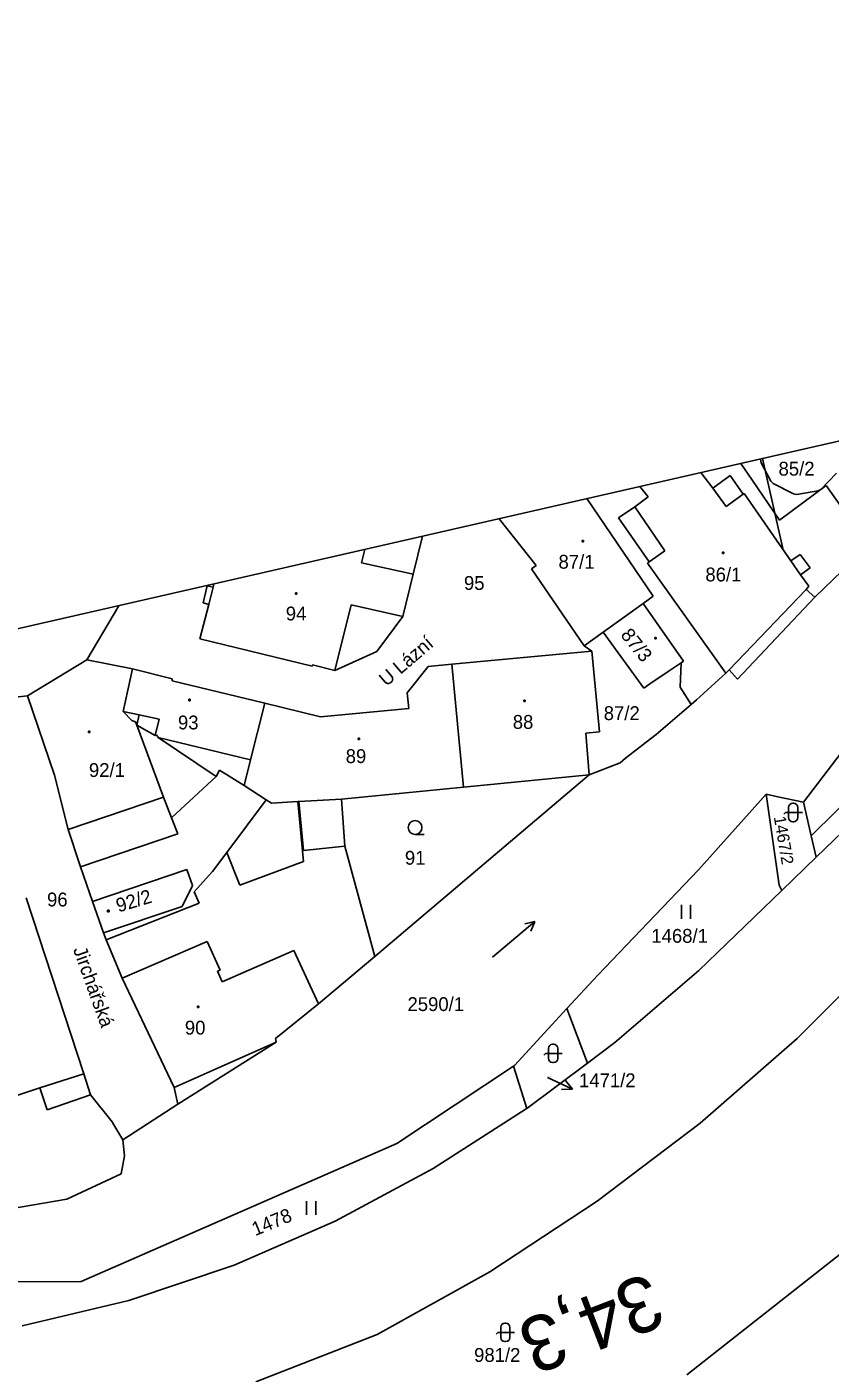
# Model space of a CAD drawing. Extents: x -805730 to -804640, y -1150889 to -1150366.
# Drawn here: x -805195.8 to -805108.7, y -1150558.7 to -1150412.8 of the extents above; entities that cross this region are included whole.
import ezdxf

# ---------------------------------------------------------------- set-up
doc = ezdxf.new("R2010")
doc.units = 0
for name, color, linetype in [('Default', 7, 'Continuous'), ('formát', 7, 'Continuous'), ('kilometráž - vrstava 7', 7, 'Continuous'), ('kn_celek - Cisla parcel pomocna', 7, 'Continuous'), ('kn_celek - Cisla pozemkovych parcel', 7, 'Continuous'), ('kn_celek - Cisla stavebnich parcel', 7, 'Continuous'), ('kn_celek - Dalsi prvky mapy popis', 7, 'Continuous'), ('kn_celek - Hranice parcel', 7, 'Continuous'), ('kn_celek - Vnitrni kresby', 7, 'Continuous'), ('kn_celek - Znacky budov', 7, 'Continuous'), ('kn_celek - Znacky kultur', 7, 'Continuous')]:
    doc.layers.add(name, color=color, linetype=linetype)

# ---------------------------------------------------------------- blocks, each defined once
blk = doc.blocks.new('304')
at = {"layer": 'Default'}
blk.add_line((-0.1, 0), (9.9, 0), dxfattribs=at)
blk.add_circle((-0.1, 7.5), 7.5, dxfattribs=at)
blk = doc.blocks.new('316')
at = {"layer": 'Default'}
for p, q in [((-5, 15.5), (-5, 4.5)), ((0.5, 20), (-0.5, 20)), ((5, 4.5), (5, 15.5)), ((-8.3, 10), (-10, 8.1)), ((-5, 10), (-8.3, 10)), ((-5, 10), (5, 10)), ((-0.5, 0), (0.5, 0)), ((10, 10), (5, 10))]:
    blk.add_line(p, q, dxfattribs=at)
for centre, start, end in [((-0.5, 15.5), 90, 180), ((0.5, 15.5), 0, 90), ((-0.5, 4.5), 180, 270), ((0.5, 4.5), 270, 0)]:
    blk.add_arc(centre, 4.5, start, end, dxfattribs=at)
blk = doc.blocks.new('306')
at = {"layer": 'Default'}
for p, q in [((-5.2, 0), (-5.2, 15)), ((4.8, 0), (4.8, 15))]:
    blk.add_line(p, q, dxfattribs=at)
blk = doc.blocks.new('802')
at = {"layer": 'Default'}
for p, q in [((-30, 0), (30, 0)), ((20, 5), (30, 0)), ((30, 0), (20, -5))]:
    blk.add_line(p, q, dxfattribs=at)
blk = doc.blocks.new('402')
at = {"layer": 'Default'}
for p, q in [((-0.8, 0.8), (0.7, 0.8)), ((-0.8, 0.8), (-0.8, -0.7)), ((0.7, 0.8), (0.7, -0.7)), ((0.7, -0.7), (-0.8, -0.7))]:
    blk.add_line(p, q, dxfattribs=at)
blk = doc.blocks.new('Z61')
at = {"layer": 'Default'}
for p, q in [((0, 0), (30, 0)), ((30, 0), (19.2, 5.3)), ((30, 0), (19.2, -5.3))]:
    blk.add_line(p, q, dxfattribs=at)

msp = doc.modelspace()

# ---------------------------------------------------------------- linework, layer by layer
at = {"layer": 'formát'}
for p, q in [((-804911.33, -1150412.76), (-805116.05, -1150459.54)), ((-805116.05, -1150459.54), (-805730.21, -1150599.91)), ((-805116.05, -1150459.54), (-805113.82, -1150469.29))]:
    msp.add_line(p, q, dxfattribs=at)
at = {"layer": 'kn_celek - Hranice parcel'}
for p, q in [((-805117.2, -1150461.8), (-805118.38, -1150460.08)), ((-805116.25, -1150459.59), (-805116.25, -1150459.6)), ((-805116.25, -1150459.6), (-805116.18, -1150459.99)), ((-805116.18, -1150459.99), (-805115.13, -1150462.01)), ((-805122.71, -1150461.07), (-805121.43, -1150462.77)), ((-805121.43, -1150462.77), (-805119.54, -1150461.39)), ((-805119.54, -1150461.39), (-805118.15, -1150463.41)), ((-805114.18, -1150466.22), (-805117.2, -1150461.8)), ((-805115.13, -1150462.01), (-805114.9, -1150462.24)), ((-805114.9, -1150462.24), (-805112.68, -1150463.36)), ((-805109.72, -1150462.89), (-805108.02, -1150461.11)), ((-805129.88, -1150464.79), (-805128.44, -1150463.7)), ((-805128.44, -1150463.7), (-805129.33, -1150462.58)), ((-805118.15, -1150463.41), (-805118.02, -1150463.32)), ((-805112.97, -1150470.62), (-805118.02, -1150463.32)), ((-805109.13, -1150462.48), (-805114.18, -1150466.22)), ((-805112.68, -1150463.36), (-805112.35, -1150463.44)), ((-805112.35, -1150463.44), (-805109.99, -1150463.04)), ((-805109.99, -1150463.04), (-805109.72, -1150462.89)), ((-805109.13, -1150462.48), (-805105.81, -1150467.16)), ((-805135.07, -1150463.89), (-805127.89, -1150474.45)), ((-805131.65, -1150465.97), (-805129.88, -1150464.79)), ((-805140.59, -1150471.14), (-805144.58, -1150466.07)), ((-805128.33, -1150470.75), (-805131.65, -1150465.97)), ((-805153.92, -1150472.09), (-805152.91, -1150467.97)), ((-805104.72, -1150469.11), (-805110.36, -1150474.57)), ((-805141.07, -1150471.5), (-805140.59, -1150471.14)), ((-805128.5, -1150470.88), (-805128.33, -1150470.75)), ((-805120.01, -1150482.82), (-805128.5, -1150470.88)), ((-805112.97, -1150470.62), (-805111.96, -1150469.93)), ((-805111.96, -1150469.93), (-805110.87, -1150471.39)), ((-805153.92, -1150472.09), (-805155.04, -1150476.68)), ((-805135.36, -1150479.83), (-805141.07, -1150471.5)), ((-805110.87, -1150471.39), (-805111.93, -1150472.13)), ((-805111.93, -1150472.13), (-805111.01, -1150473.36)), ((-805176.25, -1150473.34), (-805176.67, -1150475.17)), ((-805175.59, -1150473.5), (-805176.25, -1150473.34)), ((-805175.59, -1150473.5), (-805175.5, -1150473.13)), ((-805111.01, -1150473.36), (-805111.3, -1150473.72)), ((-805111.3, -1150473.72), (-805110.36, -1150474.57)), ((-805185.81, -1150475.49), (-805189.27, -1150481.37)), ((-805176.05, -1150475.37), (-805177.02, -1150479.09)), ((-805176.67, -1150475.17), (-805176.05, -1150475.37)), ((-805133.32, -1150478.36), (-805128.99, -1150475.24)), ((-805127.89, -1150474.45), (-805128.99, -1150475.24)), ((-805124.61, -1150481.5), (-805128.99, -1150475.24)), ((-805110.36, -1150474.57), (-805118.75, -1150483.44)), ((-805155.04, -1150476.68), (-805157.86, -1150480.45)), ((-805111.59, -1150496.78), (-805095.74, -1150475.92)), ((-805133.32, -1150478.36), (-805135.36, -1150479.83)), ((-805128.9, -1150484.42), (-805133.32, -1150478.36)), ((-805164.86, -1150482.06), (-805177.02, -1150479.09)), ((-805134.54, -1150480.41), (-805135.36, -1150479.83)), ((-805189.27, -1150481.37), (-805195.7, -1150485.27)), ((-805189.27, -1150481.37), (-805184.34, -1150482.34)), ((-805157.86, -1150480.45), (-805162.4, -1150482.51)), ((-805149.71, -1150481.83), (-805134.54, -1150480.41)), ((-805134.54, -1150480.41), (-805133.7, -1150489.18)), ((-805184.34, -1150482.34), (-805185.33, -1150486.97)), ((-805184.34, -1150482.34), (-805180.02, -1150483.43)), ((-805164.82, -1150481.92), (-805164.86, -1150482.06)), ((-805164.82, -1150481.92), (-805162.4, -1150482.51)), ((-805154.57, -1150484.94), (-805152.28, -1150482.08)), ((-805152.28, -1150482.08), (-805149.71, -1150481.83)), ((-805149.71, -1150481.83), (-805148.44, -1150495.16)), ((-805128.24, -1150483.97), (-805126.26, -1150482.62)), ((-805126.26, -1150482.62), (-805124.86, -1150481.67)), ((-805124.86, -1150481.67), (-805124.96, -1150484.31)), ((-805124.86, -1150481.67), (-805124.61, -1150481.5)), ((-805123.19, -1150485.7), (-805120.01, -1150482.82)), ((-805119.67, -1150482.46), (-805120.01, -1150482.82)), ((-805118.75, -1150483.44), (-805119.67, -1150482.46)), ((-805180.02, -1150483.43), (-805180.03, -1150483.62)), ((-805180.03, -1150483.62), (-805169.99, -1150486.07)), ((-805128.9, -1150484.42), (-805128.24, -1150483.97)), ((-805201.85, -1150485.93), (-805195.7, -1150485.27)), ((-805195.7, -1150485.27), (-805192.79, -1150493.88)), ((-805154.39, -1150486.64), (-805154.57, -1150484.94)), ((-805123.78, -1150486.2), (-805124.96, -1150484.31)), ((-805123.78, -1150486.2), (-805123.19, -1150485.7)), ((-805185.33, -1150486.97), (-805184.39, -1150487.94)), ((-805171.54, -1150492.19), (-805169.99, -1150486.07)), ((-805169.99, -1150486.07), (-805163.96, -1150487.55)), ((-805163.96, -1150487.55), (-805154.39, -1150486.64)), ((-805123.78, -1150486.2), (-805127.57, -1150489.47)), ((-805184.39, -1150487.94), (-805184, -1150488.09)), ((-805184, -1150488.09), (-805183.86, -1150488.46)), ((-805181.86, -1150489.58), (-805183.86, -1150488.46)), ((-805181.74, -1150489.49), (-805181.86, -1150489.58)), ((-805181.54, -1150489.78), (-805181.74, -1150489.49)), ((-805175.27, -1150494.02), (-805181.54, -1150489.78)), ((-805133.7, -1150489.18), (-805135.19, -1150489.32)), ((-805135.19, -1150489.32), (-805134.82, -1150493.83)), ((-805128.19, -1150489.93), (-805130.9, -1150492.03)), ((-805127.57, -1150489.47), (-805128.19, -1150489.93)), ((-805079.5, -1150489.41), (-805112.27, -1150522.42)), ((-805172.24, -1150494.99), (-805171.54, -1150492.19)), ((-805131.48, -1150492.51), (-805134.82, -1150493.83)), ((-805130.9, -1150492.03), (-805131.48, -1150492.51)), ((-805192.79, -1150493.88), (-805191.31, -1150499.74)), ((-805174.88, -1150493.33), (-805175.27, -1150494.02)), ((-805172.24, -1150494.99), (-805174.88, -1150493.33)), ((-805134.82, -1150493.83), (-805158.07, -1150513.5)), ((-805148.44, -1150495.16), (-805134.82, -1150493.83)), ((-805110.75, -1150500.43), (-805104.33, -1150494.08)), ((-805169.85, -1150496.54), (-805172.24, -1150494.99)), ((-805161.69, -1150496.45), (-805148.44, -1150495.16)), ((-805122.96, -1150504.14), (-805115.65, -1150495.91)), ((-805115.65, -1150495.91), (-805114.37, -1150496.22)), ((-805115.65, -1150495.91), (-805114.23, -1150505.8)), ((-805110.22, -1150502.75), (-805102.8, -1150495.57)), ((-805169.85, -1150496.54), (-805174.1, -1150502.23)), ((-805169.26, -1150496.89), (-805169.85, -1150496.54)), ((-805166.42, -1150496.73), (-805169.26, -1150496.89)), ((-805166.28, -1150496.72), (-805166.42, -1150496.73)), ((-805161.69, -1150496.45), (-805166.28, -1150496.72)), ((-805161.32, -1150501.56), (-805161.69, -1150496.45)), ((-805114.37, -1150496.22), (-805111.59, -1150496.78)), ((-805111.59, -1150496.78), (-805110.75, -1150500.43)), ((-805191.31, -1150499.74), (-805189.98, -1150503.81)), ((-805158.07, -1150513.5), (-805161.32, -1150501.56)), ((-805110.22, -1150502.75), (-805110.75, -1150500.43)), ((-805174.1, -1150502.23), (-805175.65, -1150504.32)), ((-805113.96, -1150506.36), (-805110.22, -1150502.75)), ((-805188.66, -1150507.54), (-805189.98, -1150503.81)), ((-805178.42, -1150504.1), (-805188.66, -1150507.54)), ((-805177.84, -1150505.82), (-805178.42, -1150504.1)), ((-805177.65, -1150506.5), (-805175.65, -1150504.32)), ((-805122.96, -1150504.14), (-805133.9, -1150515.55)), ((-805178.94, -1150508.08), (-805177.84, -1150505.82)), ((-805114.23, -1150505.8), (-805113.96, -1150506.36)), ((-805195.84, -1150507.17), (-805189.61, -1150526.23)), ((-805188.66, -1150507.54), (-805187.46, -1150510.95)), ((-805177.11, -1150507.73), (-805177.65, -1150506.5)), ((-805122.93, -1150515.03), (-805113.96, -1150506.36)), ((-805187.46, -1150510.95), (-805178.94, -1150508.08)), ((-805187.19, -1150511.72), (-805177.11, -1150507.73)), ((-805187.46, -1150510.95), (-805187.19, -1150511.72)), ((-805187.19, -1150511.72), (-805185.45, -1150515.88)), ((-805158.07, -1150513.5), (-805164.16, -1150518.66)), ((-805185.45, -1150515.88), (-805179.81, -1150527.73)), ((-805133.9, -1150515.55), (-805137.23, -1150519.16)), ((-805132.03, -1150522.85), (-805122.93, -1150515.03)), ((-805168.84, -1150522.4), (-805164.16, -1150518.66)), ((-805137.23, -1150519.16), (-805142.93, -1150525.35)), ((-805137.23, -1150519.16), (-805135.02, -1150525.08)), ((-805168.76, -1150522.8), (-805179.41, -1150529.53)), ((-805168.84, -1150522.4), (-805168.76, -1150522.8)), ((-805135.02, -1150525.08), (-805132.03, -1150522.85)), ((-805122.81, -1150531.59), (-805112.27, -1150522.42)), ((-805141.58, -1150529.98), (-805135.02, -1150525.08)), ((-805189.61, -1150526.23), (-805188.88, -1150528.51)), ((-805143.03, -1150525.41), (-805155.69, -1150533.78)), ((-805142.93, -1150525.35), (-805143.03, -1150525.41)), ((-805143.03, -1150525.41), (-805141.58, -1150529.98)), ((-805215.37, -1150534.59), (-805194.37, -1150527.77)), ((-805193.59, -1150530.15), (-805194.37, -1150527.77)), ((-805179.81, -1150527.73), (-805179.41, -1150529.53)), ((-805188.88, -1150528.51), (-805193.59, -1150530.15)), ((-805188.88, -1150528.51), (-805186.53, -1150531.45)), ((-805185.38, -1150533.39), (-805179.41, -1150529.53)), ((-805151.75, -1150536.51), (-805141.65, -1150530.03)), ((-805141.65, -1150530.03), (-805141.58, -1150529.98)), ((-805186.53, -1150531.45), (-805186.34, -1150531.78)), ((-805186.34, -1150531.78), (-805185.38, -1150533.39)), ((-805133.96, -1150540.03), (-805122.81, -1150531.59)), ((-805155.69, -1150533.78), (-805189.88, -1150548.76)), ((-805185.38, -1150533.39), (-805185.18, -1150535.11)), ((-805185.18, -1150535.11), (-805185.54, -1150537.09)), ((-805162.36, -1150542.2), (-805151.75, -1150536.51)), ((-805191.45, -1150539.81), (-805185.54, -1150537.09)), ((-805201.89, -1150541.59), (-805191.45, -1150539.81)), ((-805145.61, -1150547.7), (-805133.96, -1150540.03)), ((-805173.3, -1150546.99), (-805162.36, -1150542.2)), ((-805121.16, -1150556.44), (-805102.15, -1150541.44)), ((-805173.3, -1150546.99), (-805184.73, -1150550.79)), ((-805157.79, -1150554.48), (-805145.61, -1150547.7)), ((-805200.33, -1150548.77), (-805189.88, -1150548.76)), ((-805184.73, -1150550.79), (-805196.27, -1150553.55)), ((-805170.94, -1150559.63), (-805157.79, -1150554.48)), ((-805124.23, -1150558.85), (-805121.16, -1150556.44))]:
    msp.add_line(p, q, dxfattribs=at)
at = {"layer": 'kn_celek - Vnitrni kresby'}
for p, q in [((-805121.43, -1150462.77), (-805119.99, -1150464.74)), ((-805119.99, -1150464.74), (-805118.15, -1150463.41)), ((-805126.62, -1150469.53), (-805129.88, -1150464.79)), ((-805159.14, -1150469.39), (-805159.5, -1150470.83)), ((-805128.33, -1150470.75), (-805126.62, -1150469.53)), ((-805159.5, -1150470.83), (-805153.92, -1150472.09)), ((-805112.97, -1150470.62), (-805111.93, -1150472.13)), ((-805175.59, -1150473.5), (-805176.05, -1150475.37)), ((-805111.3, -1150473.72), (-805119.67, -1150482.46)), ((-805160.63, -1150475.39), (-805162.4, -1150482.51)), ((-805155.04, -1150476.68), (-805160.63, -1150475.39)), ((-805183.59, -1150487.33), (-805185.33, -1150486.97)), ((-805183.86, -1150488.46), (-805183.59, -1150487.33)), ((-805180.97, -1150496.25), (-805183.86, -1150488.46)), ((-805183.59, -1150487.33), (-805181.42, -1150487.78)), ((-805181.86, -1150489.58), (-805181.42, -1150487.78)), ((-805181.54, -1150489.78), (-805171.54, -1150492.19)), ((-805180.11, -1150498.5), (-805175.27, -1150494.02)), ((-805180.97, -1150496.25), (-805191.31, -1150499.74)), ((-805180.97, -1150496.25), (-805180.11, -1150498.5)), ((-805165.79, -1150503.23), (-805166.42, -1150496.73)), ((-805165.79, -1150502.01), (-805166.28, -1150496.72)), ((-805180.11, -1150498.5), (-805179.42, -1150500.23)), ((-805179.42, -1150500.23), (-805189.98, -1150503.81)), ((-805161.32, -1150501.56), (-805165.79, -1150502.01)), ((-805172.69, -1150505.77), (-805174.1, -1150502.23)), ((-805172.69, -1150505.77), (-805165.79, -1150503.23)), ((-805176.23, -1150511.9), (-805185.45, -1150515.88)), ((-805174.82, -1150514.99), (-805176.23, -1150511.9)), ((-805166.83, -1150512.88), (-805174.6, -1150516.25)), ((-805164.16, -1150518.66), (-805166.83, -1150512.88)), ((-805174.82, -1150514.99), (-805175.11, -1150515.09)), ((-805175.11, -1150515.09), (-805174.6, -1150516.25)), ((-805179.81, -1150527.73), (-805168.76, -1150522.8)), ((-805194.37, -1150527.77), (-805189.61, -1150526.23))]:
    msp.add_line(p, q, dxfattribs=at)

# ---------------------------------------------------------------- block references
at = {"layer": 'kn_celek - Cisla parcel pomocna', "xscale": 0.10000000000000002, "yscale": 0.1, "rotation": -24.44390999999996}
msp.add_blockref('Z61', (-805139.35, -1150526.64), dxfattribs=at)
at = {"layer": 'kn_celek - Znacky budov', "xscale": 0.1, "yscale": 0.10000000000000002}
for p in [(-805135.51, -1150468.49), (-805120.31, -1150469.78), (-805166.58, -1150474.19), (-805127.63, -1150479.02), (-805178.14, -1150485.72), (-805141.82, -1150485.81), (-805189.01, -1150489.18), (-805159.8, -1150489.94), (-805186.94, -1150508.59), (-805177.21, -1150518.98)]:
    msp.add_blockref('402', p, dxfattribs=at)
at = {"layer": 'kn_celek - Znacky kultur', "xscale": 0.1, "yscale": 0.10000000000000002}
for name, p in [('316', (-805112.71, -1150498.91)), ('304', (-805153.69, -1150500.29)), ('306', (-805124.31, -1150509.43)), ('316', (-805138.74, -1150525.02)), ('306', (-805164.93, -1150541.53)), ('316', (-805143.91, -1150555.26))]:
    msp.add_blockref(name, p, dxfattribs=at)
at = {"layer": 'kn_celek - Znacky kultur', "xscale": 0.10000000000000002, "yscale": 0.1, "rotation": 39.940920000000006}
msp.add_blockref('802', (-805143.01, -1150511.66), dxfattribs=at)

# ---------------------------------------------------------------- texts
at = {"layer": 'kilometráž - vrstava 7'}
msp.add_text('34,3', height=6, rotation=201.0798, dxfattribs=at).set_placement((-805128.35, -1150547.71))
at = {"layer": 'kn_celek - Cisla parcel pomocna'}
msp.add_text('1471/2', height=1.5, dxfattribs=at).set_placement((-805135.93, -1150527.69))
at = {"layer": 'kn_celek - Cisla pozemkovych parcel'}
for s, height, p in [('95', 1.5, (-805148.4, -1150473.78)), ('87/2', 1.5, (-805133.25, -1150487.89)), ('91', 1.5, (-805154.8, -1150503.57)), ('96', 1.5, (-805193.59, -1150508.09)), ('1468/1', 1.5, (-805128.09, -1150512.03)), ('2590/1', 1.5, (-805154.52, -1150519.43)), ('1471/2', 0.1, (-805139.35, -1150526.61)), ('981/2', 1.5, (-805147.3, -1150557.46))]:
    msp.add_text(s, height=height, dxfattribs=at).set_placement(p)
for s, height, rotation, p in [('1467/2', 1.3, 279.68, (-805114.82, -1150498.4)), ('1478', 1.5, 22.5, (-805171.02, -1150543.84))]:
    msp.add_text(s, height=height, rotation=rotation, dxfattribs=at).set_placement(p)
at = {"layer": 'kn_celek - Cisla stavebnich parcel'}
for s, p in [('85/2', (-805114.3, -1150461.39)), ('87/1', (-805138.15, -1150471.48)), ('86/1', (-805122.23, -1150472.86)), ('94', (-805167.71, -1150477.09)), ('93', (-805179.4, -1150488.9)), ('88', (-805143.11, -1150488.84)), ('89', (-805161.22, -1150492.55)), ('92/1', (-805189.05, -1150494.06)), ('90', (-805178.65, -1150521.98))]:
    msp.add_text(s, height=1.5, dxfattribs=at).set_placement(p)
for s, rotation, p in [('87/3', 308.7, (-805131.49, -1150478.69)), ('92/2', 16.4867, (-805185.85, -1150508.75))]:
    msp.add_text(s, height=1.5, rotation=rotation, dxfattribs=at).set_placement(p)
at = {"layer": 'kn_celek - Dalsi prvky mapy popis'}
for s, rotation, p in [('U Lázní', 40.6541, (-805156.81, -1150484.31)), ('Jirchářská', 289.8078, (-805190.79, -1150512.75))]:
    msp.add_text(s, height=1.5, rotation=rotation, dxfattribs=at).set_placement(p)

doc.saveas('drawing.dxf')
